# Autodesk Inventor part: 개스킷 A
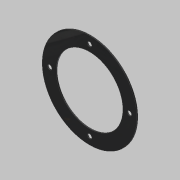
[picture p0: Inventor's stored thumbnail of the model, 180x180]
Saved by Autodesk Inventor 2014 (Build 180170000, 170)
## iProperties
Created: 2019-10
Part Number: 개스킷 A
Material: 고무
Document SubType Name: Modeling
Designer: mduedu
Density: 0.93 g/cm^3
Appearance: 고무 - 검은색 - 버전 1.1
Mass: 3.25402 g
Surface Area: 75.6338 cm^2
Volume: 3.49895 cm^3
Author: mduedu
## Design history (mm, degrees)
sketch "스케치1"
  geometry: C1 r 47.5 at (0, 0); C2 r 33.5 at (0, 0); 1 further point
  constraints: 2 centre point, 2 coincident
  dimensions: "d0" = 95 diameter of C1; "d1" = 67 diameter of C2
extrude "돌출1" new body sketch "스케치1" distance "d2" = 1; taper "d3" = 0 deg
sketch "스케치2" dims "d4" = 80
  geometry: C1 r 2.25 at (0, 40); 2 further points
  constraints: 2 vertical alignment, 1 centre point, 1 coincident, 2 other
  dimensions: "d5" = 4.5 diameter of C1
extrude "돌출2" cut sketch "스케치2" stored distance "d6" = 1; taper "d7" = 0 deg
node "솔리드1"
pattern_circular "원형 패턴1" dims angle "d9" = 360 deg
